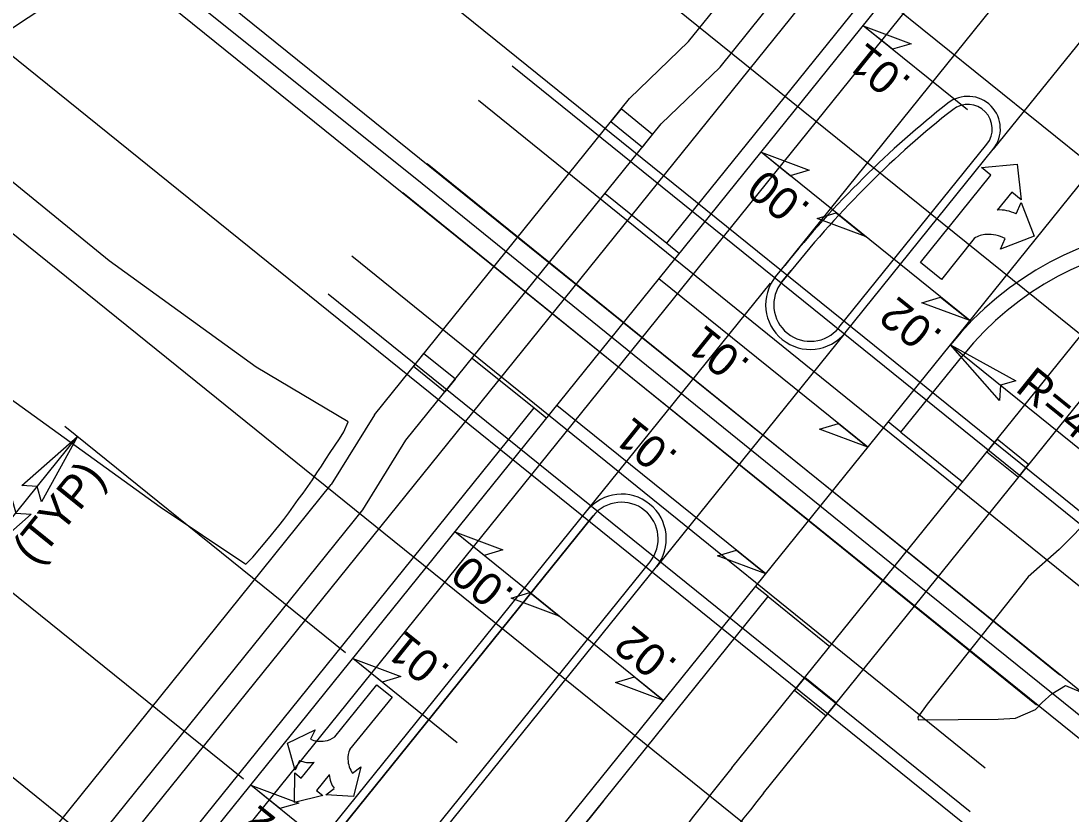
# Model space of a CAD drawing. Extents: x 1486489 to 1490134, y 497089 to 500876.
# Drawn here: x 1488715.1 to 1488844.3, y 499147.7 to 499245.3 of the extents above; entities that cross this region are included whole.
import ezdxf

# ---------------------------------------------------------------- set-up
doc = ezdxf.new("R2010")
doc.units = 0
for name, color, linetype in [('DEV PRELIMINARY STAMP CELL', 7, 'Continuous'), ('Gray Area Fill Shapes', 7, 'Continuous'), ('Old_Level_9', 7, 'Continuous'), ('Pattern 5', 7, 'Continuous'), ('Prop Conc 5in Monolithic Surface Mount Island', 7, 'Continuous'), ('Prop Conc Drive Radius Type', 7, 'Continuous'), ('Prop DSN Text', 7, 'Continuous'), ('Prop Horizontal Alignment Station Label', 7, 'Continuous'), ('Prop Rem of Exist Asph Pvmt', 7, 'Continuous'), ('Scratch_Level_0', 7, 'Continuous'), ('Scratch_Level_5', 7, 'Continuous'), ('Sheet Block Revision CELL', 7, 'Continuous'), ('Sheet Block Title CELL', 7, 'Continuous'), ('Sheet Clip Boundary CELL', 7, 'Continuous'), ('Sheet Plan CELL', 7, 'Continuous'), ('Sheet Plot Border Inside CELL', 7, 'Continuous'), ('Sheet Sticker Exception Certification CELL', 7, 'Continuous')]:
    doc.layers.add(name, color=color, linetype=linetype)

msp = doc.modelspace()

# ---------------------------------------------------------------- linework, layer by layer
at = {"layer": 'DEV PRELIMINARY STAMP CELL'}
for p, q in [((1488831.57, 499234.33), (1488818.73, 499244.68)), ((1488831.86, 499208.4), (1488806.17, 499229.12)), ((1488819.3, 499192.83), (1488793.62, 499213.55)), ((1488806.75, 499177.26), (1488781.06, 499197.98)), ((1488755.07, 499167.55), (1488720.53, 499195.4)), ((1488709.54, 499178.58), (1488722.09, 499194.15)), ((1488794.19, 499161.69), (1488768.51, 499182.41)), ((1488742.52, 499151.98), (1488707.98, 499179.84)), ((1488768.8, 499156.48), (1488755.95, 499166.84)), ((1488756.24, 499140.92), (1488743.4, 499151.27))]:
    msp.add_line(p, q, dxfattribs=at)
for points in [[(1488818.73, 499244.68), (1488824.65, 499242.47), (1488822.33, 499241.78)], [(1488806.17, 499229.12), (1488812.1, 499226.91), (1488809.77, 499226.21)], [(1488819.02, 499218.76), (1488813.09, 499220.97), (1488815.42, 499221.66)], [(1488831.86, 499208.4), (1488825.93, 499210.61), (1488828.26, 499211.3)], [(1488819.3, 499192.83), (1488813.38, 499195.04), (1488815.7, 499195.73)], [(1488715.23, 499188.12), (1488722.09, 499194.15), (1488717.65, 499186.1), (1488717.13, 499188)], [(1488716.39, 499184.61), (1488709.54, 499178.58), (1488713.97, 499186.63), (1488714.49, 499184.73)], [(1488768.51, 499182.41), (1488774.43, 499180.2), (1488772.11, 499179.51)], [(1488806.75, 499177.26), (1488800.82, 499179.47), (1488803.15, 499180.17)], [(1488781.35, 499172.05), (1488775.42, 499174.26), (1488777.75, 499174.96)], [(1488755.95, 499166.84), (1488761.88, 499164.63), (1488759.55, 499163.94)], [(1488794.19, 499161.69), (1488788.27, 499163.9), (1488790.59, 499164.6)], [(1488743.4, 499151.27), (1488749.32, 499149.06), (1488747, 499148.37)]]:
    msp.add_lwpolyline(points, close=True, dxfattribs=at)
at = {"layer": 'Old_Level_9'}
msp.add_lwpolyline([(1488890.07, 499123.82), (1488841.68, 499162.79), (1488822.88, 499177.94), (1488795.51, 499200.11), (1488763.62, 499225.91), (1488727.57, 499254.8), (1488692.17, 499283.06), (1488664.12, 499305.6), (1488617.82, 499342.84), (1488599.16, 499357.84), (1488532.76, 499411.39), (1488485.03, 499449.93), (1488450.03, 499478.08), (1488423.37, 499499.63), (1488397.39, 499520.51), (1488361.21, 499549.74)], dxfattribs=at)
at = {"layer": 'Pattern 5'}
for p, q in [((1488788.95, 499234.45), (1488787.7, 499232.89)), ((1488792.84, 499231.31), (1488788.95, 499234.45)), ((1488787.7, 499232.89), (1488791.59, 499229.75)), ((1488791.59, 499229.75), (1488792.84, 499231.31)), ((1488764.67, 499204.34), (1488763.42, 499202.79)), ((1488768.57, 499201.2), (1488764.67, 499204.34)), ((1488763.42, 499202.79), (1488767.31, 499199.65)), ((1488767.31, 499199.65), (1488768.57, 499201.2)), ((1488835.2, 499193.82), (1488833.94, 499192.27)), ((1488839.09, 499190.69), (1488835.2, 499193.82)), ((1488833.94, 499192.27), (1488837.84, 499189.13)), ((1488837.84, 499189.13), (1488839.09, 499190.69)), ((1488811.55, 499164.49), (1488810.29, 499162.94)), ((1488815.44, 499161.35), (1488811.55, 499164.49)), ((1488810.29, 499162.94), (1488814.18, 499159.8)), ((1488814.18, 499159.8), (1488815.44, 499161.35))]:
    msp.add_line(p, q, dxfattribs=at)
at = {"layer": 'Prop Conc 5in Monolithic Surface Mount Island'}
for p, q in [((1488815.75, 499207.54), (1488833.95, 499230.11)), ((1488815.75, 499207.54), (1488833.95, 499230.11)), ((1488808.74, 499213.19), (1488809.86, 499214.58)), ((1488809.86, 499214.58), (1488808.74, 499213.19)), ((1488740.18, 499128.17), (1488785.51, 499184.38)), ((1488785.51, 499184.38), (1488740.18, 499128.17)), ((1488753.47, 499130.31), (1488792.52, 499178.73)), ((1488753.47, 499130.31), (1488792.52, 499178.73))]:
    msp.add_line(p, q, dxfattribs=at)
for centre, radius, start, end in [((1488831.61, 499231.99), 3, 321.1156, 128.0567), ((1488831.61, 499231.99), 3, 321.1156, 128.0567), ((1488812.24, 499210.36), 4.5, 141.1156, 321.1156), ((1488812.24, 499210.36), 4.5, 141.1156, 321.1156), ((1488789.02, 499181.56), 4.5, 321.1156, 141.1156), ((1488789.02, 499181.56), 4.5, 321.1156, 141.1156)]:
    msp.add_arc(centre, radius, start, end, dxfattribs=at)
msp.add_ellipse((1488878.85, 499110.55), major_axis=(11.94, 143.64), ratio=0.731726, start_param=0.595692, end_param=0.823615, dxfattribs=at)
msp.add_ellipse((1488878.85, 499110.55), major_axis=(11.94, 143.64), ratio=0.731726, start_param=0.595692, end_param=0.823615, dxfattribs=at)
at = {"layer": 'Prop Conc Drive Radius Type'}
msp.add_line((1488786.78, 499149.32), (1488778, 499138.42), dxfattribs=at)
at = {"layer": 'Prop DSN Text'}
for p, q in [((1488783.32, 499290.32), (1488450, 499069.19)), ((1488566.47, 498943.86), (1488817.57, 499255.22))]:
    msp.add_line(p, q, dxfattribs=at)
at = {"layer": 'Prop Horizontal Alignment Station Label'}
for p, q in [((1488797.24, 499242.74), (1488875.71, 499340.04)), ((1488801.14, 499239.6), (1488864.05, 499317.61)), ((1488789.99, 499235.74), (1488797.24, 499242.74)), ((1488793.89, 499232.6), (1488801.14, 499239.6)), ((1488758.61, 499196.82), (1488789.99, 499235.74)), ((1488762.5, 499193.68), (1488793.89, 499232.6)), ((1488802.6, 499153.4), (1488854.57, 499217.84)), ((1488806.49, 499150.26), (1488861.37, 499218.31)), ((1488758.61, 499196.82), (1488753.3, 499188.25)), ((1488757.19, 499185.11), (1488762.5, 499193.68)), ((1488710.38, 499134.95), (1488753.3, 499188.25)), ((1488722.67, 499142.3), (1488757.19, 499185.11))]:
    msp.add_line(p, q, dxfattribs=at)
for radius in [405, 400]:
    msp.add_arc((1489117.85, 498899.16), radius, 141.1156, 147.049, dxfattribs=at)
at = {"layer": 'Prop Rem of Exist Asph Pvmt'}
for points in [[(1488755.4, 499195.95), (1488744.07, 499202.68), (1488725.99, 499215.74), (1488710.36, 499228.49), (1488687.96, 499246.41), (1488668.5, 499262.14), (1488648.61, 499278.49), (1488630.4, 499293.26), (1488610.04, 499310.33), (1488591.6, 499325.39), (1488586.28, 499329.49), (1488591.25, 499319.52)], [(1488609.01, 499284.22), (1488609.63, 499282.52), (1488611.82, 499282.27), (1488614.97, 499280.23), (1488636.47, 499262.18), (1488655.78, 499246.53), (1488675.03, 499230.53), (1488696.14, 499213.29), (1488713.83, 499198.84), (1488732.27, 499185.48), (1488742.82, 499178.43)], [(1488742.82, 499178.43), (1488743.68, 499179.31), (1488745.59, 499181.62), (1488746.87, 499183.16), (1488747.47, 499183.96), (1488748.07, 499184.76), (1488748.65, 499185.58), (1488749.24, 499186.39), (1488749.84, 499187.19), (1488750.41, 499188.01), (1488751, 499188.82), (1488751.55, 499189.66), (1488752.1, 499190.5), (1488752.64, 499191.35), (1488753.18, 499192.2), (1488754.31, 499193.86), (1488754.85, 499194.71), (1488755.4, 499195.95)], [(1488851.59, 499188.06), (1488851.59, 499188.06), (1488850.55, 499188.19), (1488849.75, 499187.55), (1488849.04, 499186.84), (1488848.34, 499186.12), (1488847.01, 499184.62), (1488845.67, 499183.13), (1488844.28, 499181.68), (1488842.85, 499180.27), (1488839.05, 499176.9), (1488839.05, 499176.9), (1488826.62, 499161.24), (1488825.46, 499159.61), (1488825.49, 499159.29)], [(1488835.33, 499159.37), (1488837.47, 499159.52), (1488839.95, 499160.56), (1488840.75, 499161.43), (1488841.95, 499162.48), (1488843.63, 499163.5), (1488848.1, 499161.65), (1488852.51, 499162.38)], [(1488825.49, 499159.29), (1488835.33, 499159.37)]]:
    msp.add_lwpolyline(points, dxfattribs=at)
at = {"layer": 'Scratch_Level_0'}
for p, q in [((1488829.46, 499205.43), (1488860.6, 499180.32)), ((1488732.3, 499137.52), (1488701.17, 499162.63))]:
    msp.add_line(p, q, dxfattribs=at)
msp.add_lwpolyline([(1488835.5, 499198.57), (1488829.46, 499205.43), (1488837.51, 499200.99), (1488835.61, 499200.47)], close=True, dxfattribs=at)
at = {"layer": 'Scratch_Level_5'}
for p, q in [((1488794.57, 499217.92), (1488886.22, 499331.56)), ((1488794.57, 499217.92), (1488796.13, 499216.66)), ((1488823.37, 499194.69), (1488831.02, 499204.17)), ((1488730.75, 499138.77), (1488778.25, 499197.68)), ((1488778.25, 499197.68), (1488779.81, 499196.42)), ((1488823.37, 499194.69), (1488821.82, 499195.94)), ((1488807.05, 499174.45), (1488805.49, 499175.71)), ((1488773.59, 499132.96), (1488807.05, 499174.45))]:
    msp.add_line(p, q, dxfattribs=at)
msp.add_arc((1488860.6, 499180.32), 38, 51.1156, 141.1156, dxfattribs=at)
at = {"layer": 'Sheet Block Revision CELL'}
for p, q in [((1488854.5, 499176.01), (1488775.54, 499239.69)), ((1488849.19, 499172.57), (1488771.4, 499235.48)), ((1488842.91, 499164.79), (1488765.11, 499227.7)), ((1488840.05, 499161.11), (1488762.13, 499224.12)), ((1488833.76, 499153.34), (1488755.84, 499216.34)), ((1488831.9, 499147.99), (1488752.94, 499211.67))]:
    msp.add_line(p, q, dxfattribs=at)
at = {"layer": 'Sheet Block Title CELL'}
for p, q in [((1488829.46, 499205.43), (1488913.13, 499309.18)), ((1488809.08, 499215.2), (1488874.37, 499296.16)), ((1488873.9, 499278.05), (1488834.73, 499229.48)), ((1488784.74, 499185.01), (1488807.33, 499213.03)), ((1488816.52, 499206.91), (1488793.3, 499178.11))]:
    msp.add_line(p, q, dxfattribs=at)
at = {"layer": 'Sheet Clip Boundary CELL'}
for p, q in [((1488786.98, 499224.04), (1488794.57, 499217.92)), ((1488770.66, 499203.8), (1488778.25, 499197.68)), ((1488823.37, 499194.69), (1488830.96, 499188.57)), ((1488807.05, 499174.45), (1488814.64, 499168.33))]:
    msp.add_line(p, q, dxfattribs=at)
at = {"layer": 'Sheet Plan CELL'}
for p, q in [((1488989.91, 499112.07), (1488678.54, 499363.17)), ((1488667.87, 499349.94), (1488979.24, 499098.84)), ((1488968.56, 499085.6), (1488657.2, 499336.7)), ((1488646.42, 499323.34), (1488957.79, 499072.24)), ((1488954.87, 499068.62), (1488643.5, 499319.72)), ((1488632.83, 499306.48), (1488944.2, 499055.38)), ((1488933.52, 499042.15), (1488622.16, 499293.25)), ((1488574.59, 498937.3), (1488825.69, 499248.67))]:
    msp.add_line(p, q, dxfattribs=at)
at = {"layer": 'Sheet Plot Border Inside CELL'}
for p, q in [((1488833.27, 499227.23), (1488837.67, 499227.67)), ((1488837.67, 499227.67), (1488838.18, 499223.28)), ((1488825.78, 499215.55), (1488834.44, 499226.29)), ((1488834.44, 499226.29), (1488833.27, 499227.23)), ((1488837.01, 499224.22), (1488835.22, 499222)), ((1488838.18, 499223.28), (1488837.01, 499224.22)), ((1488837.55, 499221.54), (1488838.15, 499222.92)), ((1488838.15, 499222.92), (1488839.76, 499218.79)), ((1488832.4, 499218.5), (1488828.35, 499213.48)), ((1488839.76, 499218.79), (1488835.63, 499217.18)), ((1488835.63, 499217.18), (1488836.2, 499218.52)), ((1488828.35, 499213.48), (1488825.78, 499215.55)), ((1488753.73, 499157.21), (1488758.91, 499163.61)), ((1488758.91, 499163.61), (1488760.79, 499162.09)), ((1488760.79, 499162.09), (1488755.57, 499155.65)), ((1488747.94, 499156.44), (1488751.33, 499158.08)), ((1488751.33, 499158.08), (1488750.77, 499156.9)), ((1488748.86, 499153.12), (1488747.94, 499156.44)), ((1488749.41, 499154.3), (1488748.86, 499153.12)), ((1488749.61, 499152.13), (1488751.21, 499154.1)), ((1488748.77, 499149.11), (1488748.83, 499152.77)), ((1488748.83, 499152.77), (1488749.61, 499152.13)), ((1488753.06, 499152.54), (1488751.49, 499150.61)), ((1488755.92, 499152.73), (1488756.96, 499153.52)), ((1488756.96, 499153.52), (1488756.03, 499149.88)), ((1488752.28, 499149.97), (1488748.77, 499149.11)), ((1488751.49, 499150.61), (1488752.28, 499149.97)), ((1488752.62, 499150.07), (1488753.66, 499150.86)), ((1488756.03, 499149.88), (1488752.62, 499150.07))]:
    msp.add_line(p, q, dxfattribs=at)
for centre, radius, start, end in [((1488835.51, 499217.59), 4.43, 62.7065, 93.5851), ((1488833.9, 499216.47), 2.52, 90.1888, 126.5008), ((1488834.17, 499214.57), 4.43, 62.8253, 93.6789)]:
    msp.add_arc(centre, radius, start, end, dxfattribs=at)
for centre, major_axis, start_param, end_param in [((1488752.73, 499160.36), (-2.52, -3.1), 0.203036, 0.742869), ((1488752.77, 499158.81), (-1.43, -1.77), 0.681955, 1.288737), ((1488757.36, 499155.1), (-1.43, -1.77), 5.025308, 5.60123), ((1488751.4, 499157.74), (-2.52, -3.1), 0.196592, 0.735719), ((1488758.89, 499155.37), (-2.52, -3.1), 5.540317, 6.085081), ((1488756.6, 499153.53), (-2.52, -3.1), 5.554392, 6.091543)]:
    msp.add_ellipse(centre, major_axis=major_axis, ratio=0.8, start_param=start_param, end_param=end_param, dxfattribs=at)
at = {"layer": 'Sheet Sticker Exception Certification CELL'}
for p, q in [((1488732.3, 499137.52), (1488887.78, 499330.31)), ((1488816.52, 499206.91), (1488834.73, 499229.48)), ((1488807.96, 499213.81), (1488809.08, 499215.2)), ((1488772.04, 499134.22), (1488829.46, 499205.43)), ((1488739.4, 499128.8), (1488784.74, 499185.01)), ((1488754.24, 499129.68), (1488793.3, 499178.11))]:
    msp.add_line(p, q, dxfattribs=at)
for centre, radius, start, end in [((1488831.61, 499231.99), 4, 321.1156, 128.0567), ((1488860.6, 499180.32), 40, 51.1156, 141.1156), ((1488812.24, 499210.36), 5.5, 141.1156, 321.1156), ((1488789.02, 499181.56), 5.5, 321.1156, 141.1156)]:
    msp.add_arc(centre, radius, start, end, dxfattribs=at)
msp.add_ellipse((1488878.85, 499110.55), major_axis=(11.94, 144.63), ratio=0.733553, start_param=0.596292, end_param=0.824214, dxfattribs=at)

# ---------------------------------------------------------------- texts
at = {"layer": 'DEV PRELIMINARY STAMP CELL'}
msp.add_text('(TYP)', height=4, rotation=51.1156, dxfattribs=at).set_placement((1488716.91, 499178.16))
at = {"layer": 'Gray Area Fill Shapes'}
for s, p in [('.01', (1488824.85, 499238.08)), ('.00', (1488812.44, 499222.55)), ('.02', (1488828.71, 499206.88)), ('.01', (1488805.03, 499203.33)), ('.01', (1488796.15, 499192.02)), ('.00', (1488776.02, 499175.11)), ('.02', (1488796.09, 499166.42)), ('.01', (1488768.13, 499165.7)), ('.02', (1488750.13, 499144.33))]:
    msp.add_text(s, height=4, rotation=141.1755, dxfattribs=at).set_placement(p)
at = {"layer": 'Scratch_Level_0'}
msp.add_text("R=40'", height=4, rotation=321.1156, dxfattribs=at).set_placement((1488837.31, 499199.84))

doc.saveas('drawing.dxf')
